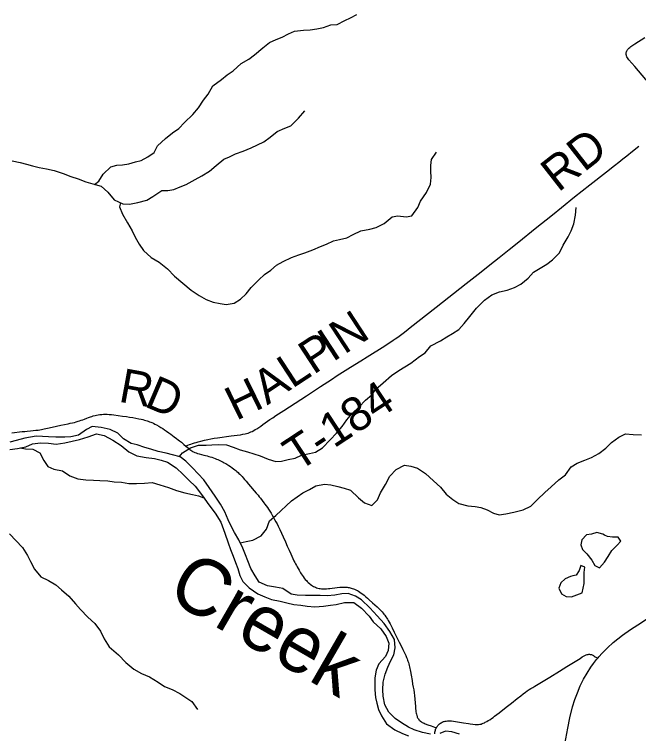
# Model space of a CAD drawing. Extents: x 0 to 34, y 0 to 22.
# Drawn here: x 20.678 to 21.722, y 18.443 to 19.645 of the extents above; entities that cross this region are included whole.
import ezdxf

# ---------------------------------------------------------------- set-up
doc = ezdxf.new("R2010")
doc.units = 0
for name, color, linetype in [('GM_X_Major_River', 7, 'Continuous'), ('GM_X_Major_River_Text', 7, 'Continuous'), ('GM_X_Minor_Lake', 7, 'Continuous'), ('GM_X_Minor_River', 7, 'Continuous'), ('GM_X_State_Route', 7, 'Continuous'), ('GM_X_Township_Road', 7, 'Continuous'), ('GM_X_Township_Road_Text', 7, 'Continuous')]:
    doc.layers.add(name, color=color, linetype=linetype)

msp = doc.modelspace()

# ---------------------------------------------------------------- linework, layer by layer
at = {"layer": 'GM_X_Major_River'}
for points in [[(21.2138, 18.6743), (21.2009, 18.6732), (21.1895, 18.6738), (21.1763, 18.6738), (21.1649, 18.6734), (21.1509, 18.6742), (21.1407, 18.676), (21.1266, 18.6855), (21.1145, 18.6873), (21.1013, 18.6896), (21.0875, 18.696), (21.0806, 18.7064), (21.0734, 18.7188), (21.0681, 18.7318), (21.0642, 18.7418), (21.0599, 18.7525), (21.0531, 18.7664), (21.0463, 18.7787), (21.0405, 18.7895), (21.0355, 18.8003), (21.0299, 18.8137), (21.0227, 18.8264), (21.0139, 18.8396), (21.0038, 18.8542), (20.995, 18.867), (20.9851, 18.8768), (20.9759, 18.8869), (20.9649, 18.8982), (20.9552, 18.9053), (20.9424, 18.9087), (20.9319, 18.9116), (20.9184, 18.9146), (20.9063, 18.9184), (20.8962, 18.9213), (20.8831, 18.9255), (20.8733, 18.928), (20.8603, 18.9356), (20.8511, 18.9453), (20.838, 18.9514), (20.8233, 18.9545), (20.8082, 18.956), (20.7986, 18.951), (20.7854, 18.9418), (20.7721, 18.9388), (20.7622, 18.9383), (20.7471, 18.9383), (20.735, 18.9391), (20.7251, 18.9393), (20.7142, 18.94), (20.7046, 18.9384), (20.6951, 18.9364), (20.681, 18.9326), (20.6703, 18.9302)], [(20.6703, 18.9177), (20.6833, 18.9196), (20.697, 18.9223), (20.7081, 18.9273), (20.7218, 18.9288), (20.7347, 18.9281), (20.7479, 18.9269), (20.7623, 18.9288), (20.7867, 18.9342), (20.8013, 18.9391), (20.815, 18.9441), (20.8282, 18.9414), (20.8428, 18.9334), (20.8565, 18.9243), (20.8695, 18.9137), (20.8825, 18.9073), (20.8984, 18.9042), (20.912, 18.9027), (20.9236, 18.8997), (20.9341, 18.8964), (20.9486, 18.8869), (20.9601, 18.8759), (20.9704, 18.8658), (20.98, 18.8564), (20.9924, 18.8405), (21.0033, 18.8254), (21.0139, 18.8115), (21.0233, 18.796), (21.0296, 18.7777), (21.0352, 18.7616), (21.0394, 18.7505), (21.044, 18.7393), (21.0475, 18.729), (21.0514, 18.7186), (21.0552, 18.7071), (21.0599, 18.6972), (21.0706, 18.6866), (21.085, 18.6764), (21.0966, 18.6715), (21.1079, 18.667), (21.1222, 18.6639), (21.1335, 18.6614), (21.1455, 18.6587), (21.1568, 18.6577), (21.1678, 18.6559), (21.1806, 18.6547), (21.1951, 18.6559), (21.2065, 18.6574), (21.2163, 18.6583), (21.2301, 18.6617), (21.2456, 18.6621), (21.2582, 18.6522), (21.2711, 18.639), (21.278, 18.6293), (21.2906, 18.6176), (21.2997, 18.6048), (21.3039, 18.5937), (21.3032, 18.5819), (21.2983, 18.5718), (21.2874, 18.5596), (21.2829, 18.5487), (21.281, 18.5359), (21.2807, 18.526)], [(21.3738, 18.4415), (21.3602, 18.4445), (21.3467, 18.4487), (21.337, 18.4532), (21.3251, 18.4607), (21.3147, 18.4678), (21.304, 18.4783), (21.2972, 18.4907), (21.2949, 18.5052), (21.2941, 18.5158), (21.2948, 18.5287), (21.2979, 18.5419), (21.3024, 18.5535), (21.3072, 18.5636), (21.3124, 18.5741), (21.315, 18.5862), (21.3135, 18.6002), (21.306, 18.6133), (21.2961, 18.6269), (21.2848, 18.6397), (21.2726, 18.653), (21.2582, 18.6663), (21.2486, 18.6722), (21.2362, 18.6771), (21.2256, 18.6763), (21.2138, 18.6743)], [(21.2807, 18.526), (21.2808, 18.5158), (21.282, 18.5032), (21.284, 18.4933), (21.2871, 18.483), (21.2917, 18.4722), (21.3, 18.4591), (21.3141, 18.4492), (21.3268, 18.4428), (21.337, 18.4387)], [(21.4226, 18.4417), (21.4095, 18.4458), (21.3989, 18.4465), (21.3893, 18.4426)]]:
    msp.add_lwpolyline(points, dxfattribs=at)
at = {"layer": 'GM_X_Minor_Lake'}
for points in [[(21.6651, 18.7745), (21.6618, 18.7759), (21.652, 18.7788), (21.6429, 18.7763), (21.6345, 18.7753), (21.6268, 18.7668), (21.6254, 18.7585), (21.6279, 18.7504), (21.6351, 18.743)], [(21.6351, 18.743), (21.6439, 18.7327), (21.6486, 18.7235), (21.6565, 18.7199), (21.665, 18.7296), (21.6709, 18.7386), (21.6771, 18.7487), (21.686, 18.7576), (21.6923, 18.7647), (21.6875, 18.7709), (21.678, 18.7711), (21.6701, 18.7724), (21.6651, 18.7745)], [(21.6273, 18.6781), (21.6306, 18.6939), (21.6309, 18.7121), (21.6319, 18.7211), (21.6255, 18.7239), (21.6227, 18.7153), (21.6172, 18.7074), (21.6118, 18.7062)], [(21.6118, 18.7062), (21.6081, 18.7053), (21.5989, 18.7017), (21.5919, 18.6946), (21.5887, 18.6856), (21.5931, 18.6764), (21.6009, 18.6717), (21.6096, 18.6711), (21.6273, 18.6781)]]:
    msp.add_lwpolyline(points, dxfattribs=at)
at = {"layer": 'GM_X_Minor_River'}
for points in [[(20.8119, 19.3611), (20.8192, 19.3666), (20.8263, 19.3782), (20.839, 19.3905), (20.8493, 19.3929), (20.8588, 19.3935), (20.8691, 19.3956), (20.8805, 19.3988), (20.89, 19.4012), (20.9011, 19.4071), (20.9115, 19.4145), (20.9174, 19.4254), (20.9309, 19.4376), (20.9421, 19.4473), (20.9529, 19.4543), (20.9622, 19.4647), (20.9765, 19.4777), (20.9858, 19.4893), (20.994, 19.502), (21.0022, 19.5117), (21.01, 19.5256), (21.0243, 19.5363), (21.0339, 19.5441), (21.0439, 19.5511), (21.0574, 19.563), (21.07, 19.5707), (21.0797, 19.5777), (21.0935, 19.5892), (21.1043, 19.5981), (21.1158, 19.6032), (21.1257, 19.6072), (21.1361, 19.6127), (21.1464, 19.6174), (21.1612, 19.619), (21.1726, 19.6195), (21.1836, 19.6212), (21.195, 19.6233), (21.2072, 19.6276), (21.2175, 19.6285), (21.2305, 19.6351), (21.24, 19.6398), (21.2504, 19.6453)], [(20.6741, 19.4002), (20.6877, 19.3976), (20.6982, 19.3948), (20.708, 19.3919), (20.7193, 19.3894), (20.7318, 19.3869), (20.7446, 19.3844), (20.7596, 19.3791), (20.7724, 19.374), (20.7845, 19.3703), (20.7972, 19.3655), (20.8093, 19.3619), (20.8228, 19.3578), (20.8344, 19.3481), (20.8447, 19.3354), (20.8594, 19.3286), (20.8707, 19.328), (20.8844, 19.3308), (20.8996, 19.3347), (20.9096, 19.3409), (20.9246, 19.3509), (20.9348, 19.351), (20.9447, 19.3527), (20.955, 19.3567), (20.965, 19.3611), (20.9803, 19.3691), (20.9914, 19.3753), (21.0041, 19.3834), (21.0153, 19.3927), (21.028, 19.4031), (21.0375, 19.4071), (21.0475, 19.4122), (21.0608, 19.4165), (21.0738, 19.4223), (21.0845, 19.427), (21.0949, 19.4321), (21.1056, 19.4402), (21.1176, 19.4495), (21.1302, 19.4549), (21.1405, 19.4589), (21.1529, 19.4719), (21.1637, 19.4839)], [(20.8556, 19.3304), (20.8536, 19.3234), (20.8586, 19.3112), (20.8671, 19.297), (20.8747, 19.2835), (20.8798, 19.2728), (20.8864, 19.2613), (20.8938, 19.2505), (20.9064, 19.2389), (20.9199, 19.2307), (20.9337, 19.2198), (20.9459, 19.2078), (20.9597, 19.1957), (20.9735, 19.1841), (20.9869, 19.1755), (20.9989, 19.1684), (21.0102, 19.164), (21.0219, 19.1619), (21.0321, 19.1602), (21.0454, 19.1622), (21.0561, 19.1692), (21.0658, 19.1781), (21.074, 19.1886), (21.0867, 19.2012), (21.0964, 19.2105), (21.1067, 19.2175), (21.1164, 19.226), (21.1275, 19.2319), (21.1413, 19.2388), (21.1535, 19.2431), (21.1634, 19.2464), (21.1772, 19.2518), (21.1898, 19.2572), (21.1997, 19.2612), (21.2116, 19.2667), (21.2218, 19.2691), (21.234, 19.2715), (21.2444, 19.2774), (21.2574, 19.2832), (21.2722, 19.2863), (21.2832, 19.2892), (21.2963, 19.2957), (21.3097, 19.3068), (21.3192, 19.3082), (21.3329, 19.3068), (21.3424, 19.3085), (21.3525, 19.3223), (21.3573, 19.3332), (21.3674, 19.3474), (21.3741, 19.3613), (21.3747, 19.3723), (21.3742, 19.383), (21.3744, 19.3925), (21.3757, 19.4027), (21.3836, 19.415)], [(20.9535, 18.9057), (20.9588, 18.9124), (20.9722, 18.9204), (20.986, 18.9251), (20.9985, 18.9248), (21.0079, 18.9258), (21.0189, 18.9263), (21.0329, 18.9253), (21.0439, 18.9217), (21.0555, 18.9169), (21.0676, 18.9136), (21.0785, 18.9104), (21.089, 18.9071), (21.1022, 18.9016), (21.1153, 18.8979), (21.1248, 18.8981), (21.1359, 18.9009), (21.1473, 18.9033), (21.158, 18.908), (21.1717, 18.9108), (21.1816, 18.9133), (21.1931, 18.9206), (21.2059, 18.934), (21.2167, 18.9448), (21.226, 18.9564), (21.2338, 18.9676), (21.2424, 18.9773), (21.2544, 18.9892), (21.2652, 19.0004), (21.2756, 19.0089), (21.2822, 19.0187), (21.2946, 19.029), (21.3085, 19.0413), (21.3208, 19.0498), (21.3307, 19.056), (21.3411, 19.0619), (21.3553, 19.073), (21.3649, 19.0796), (21.3743, 19.0912), (21.3907, 19.0996), (21.4011, 19.1059), (21.4107, 19.1117), (21.4214, 19.1184), (21.43, 19.1284), (21.4397, 19.14), (21.4506, 19.1542), (21.4641, 19.1676), (21.4764, 19.1761), (21.4894, 19.1811), (21.502, 19.1839), (21.5146, 19.1886), (21.5249, 19.1941), (21.5372, 19.2045), (21.5462, 19.2145), (21.5684, 19.2278), (21.578, 19.2348), (21.5896, 19.2467), (21.5959, 19.2595), (21.6038, 19.2733), (21.6093, 19.2835), (21.6137, 19.2952), (21.6163, 19.3095), (21.6173, 19.3224)], [(21.0555, 18.7616), (21.0656, 18.7638), (21.0767, 18.7662), (21.0908, 18.7732), (21.0994, 18.7844), (21.1046, 18.7983), (21.1154, 18.8072), (21.1413, 18.8321), (21.1509, 18.8384), (21.1605, 18.8454), (21.1716, 18.8509), (21.1823, 18.8571), (21.1964, 18.8599), (21.207, 18.8585), (21.2187, 18.856), (21.2296, 18.8531), (21.2398, 18.8495), (21.2535, 18.8367), (21.2636, 18.8286), (21.2756, 18.8242), (21.2853, 18.8335), (21.2904, 18.8455), (21.2983, 18.859), (21.3058, 18.8729), (21.3166, 18.8844), (21.3304, 18.8914), (21.341, 18.89), (21.3523, 18.8864), (21.3653, 18.8774), (21.3791, 18.8654), (21.3906, 18.8545), (21.4002, 18.8429), (21.4111, 18.834), (21.4215, 18.8274), (21.4362, 18.8233), (21.4483, 18.8226), (21.4581, 18.8206), (21.4687, 18.8169), (21.4792, 18.811), (21.4889, 18.8082), (21.5, 18.8099), (21.5133, 18.813), (21.5289, 18.8169), (21.5415, 18.8227), (21.5527, 18.8342), (21.5651, 18.8458), (21.5755, 18.8554), (21.5886, 18.8669), (21.5994, 18.8754), (21.6092, 18.8885), (21.6191, 18.8948), (21.6321, 18.8998), (21.6432, 18.9045), (21.6551, 18.9111), (21.667, 18.92), (21.6767, 18.9297), (21.6886, 18.9382), (21.6997, 18.944), (21.713, 18.943), (21.7266, 18.942)], [(20.6874, 18.9204), (20.6964, 18.9187), (20.7089, 18.9184), (20.7205, 18.9121), (20.7274, 18.8991), (20.7341, 18.8895), (20.7438, 18.8847), (20.7582, 18.8822), (20.7709, 18.8736), (20.784, 18.8687), (20.7972, 18.867), (20.8101, 18.8667), (20.8207, 18.8661), (20.8343, 18.8651), (20.8449, 18.8638), (20.857, 18.8631), (20.8691, 18.8606), (20.8824, 18.8607), (20.8956, 18.8612), (20.9082, 18.8625), (20.9213, 18.8585), (20.9356, 18.854), (20.9488, 18.8492), (20.9627, 18.8455), (20.9759, 18.8426), (20.9857, 18.8405), (20.995, 18.8369)], [(20.6696, 18.7769), (20.6915, 18.7541), (20.6996, 18.7407), (20.705, 18.7307), (20.7116, 18.7177), (20.7219, 18.7049), (20.7347, 18.6986), (20.747, 18.6915), (20.7567, 18.683), (20.769, 18.6725), (20.7801, 18.6598), (20.7886, 18.6501), (20.8009, 18.6374), (20.8124, 18.6269), (20.822, 18.6138), (20.8282, 18.6012), (20.8362, 18.5877), (20.8518, 18.5741), (20.8641, 18.5614), (20.8775, 18.5505), (20.8906, 18.543), (20.9041, 18.5378), (20.9184, 18.5288), (20.9288, 18.5214), (20.942, 18.5162), (20.9547, 18.5099), (20.9644, 18.5032), (20.9745, 18.4966), (20.9841, 18.4831)]]:
    msp.add_lwpolyline(points, dxfattribs=at)
at = {"layer": 'GM_X_State_Route'}
msp.add_lwpolyline([(21.5983, 18.4252), (21.6033, 18.452), (21.6069, 18.469), (21.6116, 18.4876), (21.6152, 18.4995), (21.6195, 18.5111), (21.6243, 18.5225), (21.6299, 18.5335), (21.6357, 18.5438), (21.6419, 18.5536), (21.6462, 18.5599), (21.6513, 18.5664), (21.653, 18.5684), (21.654, 18.5695), (21.6553, 18.5709), (21.6607, 18.5769), (21.6698, 18.5862), (21.6795, 18.5949), (21.695, 18.6074), (21.7081, 18.6165), (21.7206, 18.6247), (21.7368, 18.635)], dxfattribs=at)
at = {"layer": 'GM_X_Township_Road'}
for points in [[(21.7399, 19.5294), (21.7153, 19.5582), (21.7058, 19.5692), (21.7045, 19.5709), (21.7032, 19.5726), (21.7023, 19.5742), (21.7018, 19.5754), (21.7014, 19.5766), (21.701, 19.5782), (21.7009, 19.5792), (21.7009, 19.5805), (21.701, 19.5815), (21.7014, 19.5829), (21.7021, 19.5844), (21.7028, 19.5855), (21.7036, 19.5866), (21.7046, 19.5876), (21.7058, 19.5889), (21.7074, 19.5902), (21.7091, 19.5915), (21.7155, 19.5958), (21.7321, 19.6065)], [(20.9647, 18.9235), (20.9679, 18.9248), (20.9706, 18.9259), (20.9732, 18.9269), (20.976, 18.9279), (20.9789, 18.9288), (20.9818, 18.9297), (20.9853, 18.9307), (20.99, 18.9319), (20.9961, 18.9334), (21.0015, 18.9346), (21.0066, 18.9357), (21.0118, 18.9366), (21.0177, 18.9375), (21.0254, 18.9385), (21.0328, 18.9394), (21.0404, 18.9404), (21.0507, 18.9417), (21.0558, 18.9424), (21.0601, 18.9432), (21.064, 18.9439), (21.0663, 18.9445), (21.069, 18.9453), (21.0712, 18.9461), (21.0733, 18.947), (21.0755, 18.9481), (21.0781, 18.9494), (21.0807, 18.951), (21.0833, 18.9525), (21.0866, 18.9547), (21.0898, 18.9569), (21.0935, 18.9595), (21.0971, 18.9621), (21.1014, 18.9651), (21.1054, 18.9679), (21.11, 18.9709), (21.1154, 18.9745), (21.1284, 18.9829), (21.1664, 19.0076), (21.1899, 19.0229), (21.208, 19.0348), (21.2178, 19.0412), (21.2398, 19.0553), (21.2572, 19.0661), (21.2677, 19.0727), (21.2972, 19.0913), (21.3033, 19.0951), (21.3075, 19.0979), (21.3116, 19.1006), (21.315, 19.1029), (21.3193, 19.1058), (21.3235, 19.1089), (21.328, 19.1123), (21.3333, 19.1164), (21.3399, 19.1215), (21.3831, 19.1557), (21.4337, 19.1955), (21.4586, 19.215), (21.4731, 19.2264), (21.4885, 19.2387), (21.5055, 19.2524), (21.5213, 19.2651), (21.5489, 19.2871), (21.5776, 19.3101), (21.5929, 19.3225), (21.6147, 19.34), (21.6405, 19.3601), (21.6682, 19.382), (21.6816, 19.3925), (21.689, 19.3984), (21.6954, 19.4036), (21.702, 19.4088), (21.7114, 19.4164), (21.7221, 19.4248)], [(20.6738, 18.9456), (20.6908, 18.9476), (20.6951, 18.948), (20.6992, 18.9484), (20.705, 18.9489), (20.7095, 18.9493), (20.714, 18.9498), (20.7178, 18.9503), (20.7233, 18.9512), (20.7278, 18.9521), (20.7359, 18.9538), (20.7481, 18.9566), (20.7557, 18.9582), (20.7678, 18.9608), (20.7713, 18.9615), (20.7751, 18.9623), (20.7786, 18.9631), (20.7814, 18.9639), (20.7846, 18.9649), (20.7868, 18.9656), (20.7894, 18.9665), (20.7925, 18.9676), (20.7953, 18.9686), (20.799, 18.97), (20.8021, 18.9712), (20.805, 18.9723), (20.8073, 18.9731), (20.8098, 18.9739), (20.8128, 18.9747), (20.8152, 18.9753), (20.8181, 18.9759), (20.8206, 18.9762), (20.8239, 18.9765), (20.8272, 18.9767), (20.83, 18.9767), (20.8331, 18.9766), (20.8364, 18.9764), (20.8403, 18.976), (20.8442, 18.9756), (20.8513, 18.9747), (20.8585, 18.9737), (20.8653, 18.9728), (20.8706, 18.9719), (20.8759, 18.971), (20.8808, 18.9701), (20.8862, 18.9691), (20.8898, 18.9683), (20.8926, 18.9677), (20.8955, 18.9669), (20.898, 18.9662), (20.9001, 18.9655), (20.9018, 18.9649), (20.9039, 18.9642), (20.9059, 18.9635), (20.908, 18.9626), (20.9105, 18.9615), (20.913, 18.9603), (20.9155, 18.9589), (20.9197, 18.9566), (20.923, 18.9545), (20.926, 18.9526), (20.9291, 18.9505), (20.9322, 18.9483), (20.9361, 18.9455), (20.9394, 18.9433), (20.9422, 18.9412), (20.9454, 18.9388), (20.9491, 18.9361), (20.9518, 18.934), (20.9541, 18.9323), (20.9558, 18.9309), (20.9572, 18.9298), (20.9583, 18.9288), (20.9597, 18.9277), (20.9615, 18.9261), (20.9647, 18.9235)], [(20.9647, 18.9235), (20.9691, 18.9197), (20.9714, 18.9178), (20.9731, 18.9164), (20.9745, 18.9155), (20.976, 18.9146), (20.9777, 18.9137), (20.9796, 18.9127), (20.9819, 18.9119), (20.9843, 18.9113), (20.987, 18.9105), (20.991, 18.9095), (20.9948, 18.9085), (20.9976, 18.9077), (21.0004, 18.907), (21.0031, 18.9062), (21.0055, 18.9055), (21.0082, 18.9047), (21.0111, 18.9037), (21.0139, 18.9027), (21.0162, 18.9018), (21.0184, 18.9009), (21.0204, 18.9), (21.0227, 18.8989), (21.0248, 18.8979), (21.027, 18.8968), (21.029, 18.8957), (21.0313, 18.8944), (21.0332, 18.8933), (21.035, 18.8922), (21.0368, 18.891), (21.0392, 18.8894), (21.0422, 18.8873), (21.0444, 18.8856), (21.0465, 18.884), (21.0484, 18.8824), (21.0502, 18.8809), (21.0519, 18.8794), (21.0535, 18.8778), (21.0549, 18.8765), (21.057, 18.8744), (21.0589, 18.8724), (21.0607, 18.8704), (21.063, 18.8678), (21.0654, 18.8649), (21.0695, 18.86), (21.073, 18.8556), (21.0791, 18.8486), (21.0824, 18.8448), (21.0854, 18.8411), (21.0875, 18.8385), (21.0895, 18.8361), (21.0923, 18.8324), (21.0951, 18.8287), (21.0969, 18.8264), (21.0988, 18.8238), (21.101, 18.8207), (21.1031, 18.8177), (21.105, 18.8148), (21.1071, 18.8114), (21.1091, 18.808), (21.1114, 18.804), (21.1132, 18.8008), (21.1153, 18.7969), (21.1172, 18.7932), (21.119, 18.7893), (21.1218, 18.7837), (21.1246, 18.7778), (21.1273, 18.7719), (21.1311, 18.7636), (21.1343, 18.7562), (21.1374, 18.7493), (21.14, 18.7433), (21.1417, 18.7395), (21.1436, 18.7356), (21.1455, 18.7317), (21.1469, 18.7288), (21.1481, 18.7265), (21.1495, 18.7237), (21.1508, 18.7214), (21.1523, 18.7186), (21.154, 18.7157), (21.1552, 18.7137), (21.1565, 18.7117), (21.1578, 18.7096), (21.1591, 18.7077), (21.1608, 18.7053), (21.1626, 18.7028), (21.1644, 18.7006), (21.1662, 18.6985), (21.1678, 18.6968), (21.1693, 18.6954), (21.1712, 18.6936), (21.1728, 18.6923), (21.1746, 18.691), (21.1764, 18.6898), (21.1782, 18.6888), (21.18, 18.6879), (21.1816, 18.6873), (21.1834, 18.6866), (21.1855, 18.686), (21.1874, 18.6855), (21.1894, 18.6852), (21.1914, 18.685), (21.194, 18.6848), (21.1965, 18.6848), (21.1998, 18.685), (21.2031, 18.6853), (21.2057, 18.6855), (21.2094, 18.6859), (21.2138, 18.6865), (21.2179, 18.6869), (21.2222, 18.6873), (21.2251, 18.6875), (21.228, 18.6876), (21.2298, 18.6876), (21.2314, 18.6875), (21.2332, 18.6874), (21.2347, 18.6873), (21.2362, 18.687), (21.2379, 18.6867), (21.2395, 18.6864), (21.2414, 18.6858), (21.2431, 18.6853), (21.245, 18.6846), (21.2466, 18.684), (21.2488, 18.6831), (21.25, 18.6825), (21.2516, 18.6817), (21.2532, 18.6807), (21.2554, 18.6793), (21.2581, 18.6774), (21.2604, 18.6757), (21.2627, 18.6739), (21.2659, 18.6712), (21.2685, 18.669), (21.2715, 18.6663), (21.277, 18.6615), (21.2807, 18.6581), (21.2846, 18.6545), (21.2872, 18.652), (21.2891, 18.6501), (21.2914, 18.6477), (21.293, 18.6461), (21.2946, 18.6443), (21.2959, 18.6425), (21.2975, 18.6405), (21.2992, 18.6381), (21.3007, 18.6359), (21.302, 18.6338), (21.3033, 18.6316), (21.3047, 18.6291), (21.3063, 18.6264), (21.308, 18.623), (21.3097, 18.6196), (21.3132, 18.6125), (21.3177, 18.6034), (21.3217, 18.5954), (21.3247, 18.5893), (21.3275, 18.5835), (21.3292, 18.5802), (21.3304, 18.5776), (21.3315, 18.5754), (21.3324, 18.5733), (21.3331, 18.5717), (21.3339, 18.5697), (21.3347, 18.5677), (21.3355, 18.5654), (21.3361, 18.5636), (21.3368, 18.5614), (21.3374, 18.5594), (21.3381, 18.5568), (21.3388, 18.5542), (21.3393, 18.5516), (21.3398, 18.5492), (21.3404, 18.5463), (21.3415, 18.5402), (21.343, 18.5316), (21.344, 18.5254), (21.3449, 18.5205), (21.3457, 18.5158), (21.3464, 18.5109), (21.347, 18.5064), (21.3476, 18.5003), (21.3481, 18.4942), (21.3486, 18.4879), (21.349, 18.4841), (21.3492, 18.4814), (21.3495, 18.479), (21.3499, 18.4771), (21.3503, 18.475), (21.3508, 18.4731), (21.3513, 18.4716), (21.3518, 18.4703), (21.3523, 18.4693), (21.3528, 18.4683), (21.3536, 18.4671), (21.3545, 18.4659), (21.3553, 18.465), (21.3561, 18.4642), (21.3573, 18.4633), (21.3588, 18.4622), (21.3601, 18.4615), (21.3615, 18.4607), (21.363, 18.46), (21.3649, 18.4592), (21.3696, 18.4573), (21.3747, 18.4556), (21.3804, 18.4537), (21.3838, 18.4525)], [(21.3838, 18.4525), (21.3846, 18.4539), (21.3853, 18.455), (21.3862, 18.4562), (21.3871, 18.4571), (21.388, 18.458), (21.3891, 18.459), (21.3905, 18.4601), (21.3918, 18.4609), (21.3931, 18.4617), (21.3944, 18.4622), (21.3958, 18.4627), (21.3969, 18.4631), (21.3983, 18.4634), (21.4001, 18.4637), (21.4021, 18.464), (21.4039, 18.4641), (21.4061, 18.4641), (21.4089, 18.4639), (21.4125, 18.4635), (21.4292, 18.4607), (21.4372, 18.4593), (21.4404, 18.4588), (21.4449, 18.4582), (21.4487, 18.4579), (21.451, 18.4577), (21.4524, 18.4577), (21.4541, 18.4579), (21.4563, 18.4582), (21.4584, 18.4587), (21.4603, 18.4593), (21.4619, 18.4599), (21.464, 18.4608), (21.4655, 18.4616), (21.4678, 18.4629), (21.4704, 18.4644), (21.4728, 18.4659), (21.4759, 18.468), (21.4784, 18.4698), (21.481, 18.4717), (21.4885, 18.4775), (21.5004, 18.4868), (21.5092, 18.4938), (21.5188, 18.5014), (21.5248, 18.506), (21.529, 18.5092), (21.5329, 18.5121), (21.5356, 18.5139), (21.5389, 18.5162), (21.5416, 18.5179), (21.5448, 18.5199), (21.5481, 18.5218), (21.5735, 18.5372), (21.5896, 18.5472), (21.6018, 18.5548), (21.6157, 18.5633), (21.624, 18.5685), (21.6277, 18.5708), (21.63, 18.5722), (21.6318, 18.5732), (21.6332, 18.5739), (21.6344, 18.5743), (21.636, 18.5749), (21.6373, 18.5751), (21.6387, 18.5753), (21.6397, 18.5753), (21.6406, 18.5752), (21.6416, 18.575), (21.6429, 18.5747), (21.6442, 18.5743), (21.6455, 18.5737), (21.6467, 18.5731), (21.6478, 18.5724), (21.6493, 18.5712), (21.6512, 18.5698), (21.653, 18.5684)], [(21.3809, 18.4425), (21.3813, 18.445), (21.3816, 18.4468), (21.382, 18.4483), (21.3824, 18.4496), (21.383, 18.451), (21.3838, 18.4525)]]:
    msp.add_lwpolyline(points, dxfattribs=at)

# ---------------------------------------------------------------- texts
at = {"layer": 'GM_X_Major_River_Text'}
msp.add_text('Creek', height=0.09469, rotation=330.0034, dxfattribs=at).set_placement((20.9294, 18.6702))
at = {"layer": 'GM_X_Township_Road_Text'}
for s, height, rotation, p in [('RD', 0.05682, 38.0427, (21.5874, 19.3468)), ('N', 0.0568, 33.1816, (21.2295, 19.0758)), ('I', 0.0568, 33.1726, (21.21, 19.0631)), ('P', 0.0568, 33.1896, (21.1779, 19.0421)), ('L', 0.0568, 33.1778, (21.1423, 19.0188)), ('R', 0.0568, 349.6634, (20.8507, 18.998)), ('A', 0.0568, 33.564, (21.1007, 18.9912)), ('D', 0.0568, 336.8483, (20.8934, 18.9906)), ('H', 0.0568, 26.1016, (21.0488, 18.9652)), ('T-184', 0.05682, 33.3152, (21.1523, 18.8797))]:
    msp.add_text(s, height=height, rotation=rotation, dxfattribs=at).set_placement(p)

doc.saveas('drawing.dxf')
